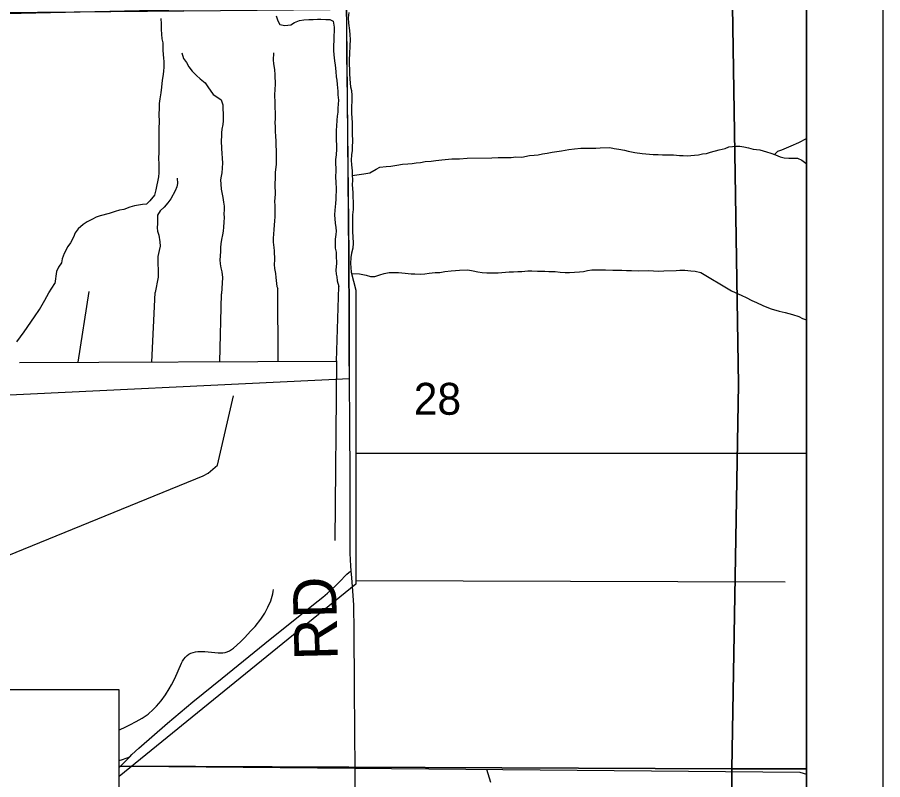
# Model space of a CAD drawing. Extents: x 0 to 34, y 0 to 22.
# Drawn here: x 7.864 to 9, y 16.861 to 17.862 of the extents above; entities that cross this region are included whole.
import ezdxf

# ---------------------------------------------------------------- set-up
doc = ezdxf.new("R2010")
doc.units = 0
for name, color, linetype in [('Default', 7, 'Continuous'), ('GM_X_County_Road', 7, 'Continuous'), ('GM_X_County_Road_Text', 7, 'Continuous'), ('GM_X_Minor_River', 7, 'Continuous'), ('GM_X_Section', 7, 'Continuous'), ('GM_X_Section_Text', 7, 'Continuous'), ('GM_X_State_Route', 7, 'Continuous'), ('GM_X_Township_Road', 7, 'Continuous'), ('SH_Data', 7, 'Continuous'), ('SH_Text', 7, 'Continuous')]:
    doc.layers.add(name, color=color, linetype=linetype)

msp = doc.modelspace()

# ---------------------------------------------------------------- linework, layer by layer
at = {"layer": 'Default'}
msp.add_lwpolyline([(7.7898, 17.3636), (8.3, 17.3879), (8.2997, 17.4193), (8.2996, 17.4628), (8.2992, 17.5498), (8.2973, 17.7551), (8.2966, 17.8142), (8.2964, 17.8483), (8.296, 17.8766), (8.2922, 18.636), (8.2732, 18.6304), (8.2109, 18.6013), (8.1114, 18.5961), (8.102, 18.6855), (8.2128, 18.6932), (8.2343, 18.6339), (8.2922, 18.6449), (8.2909, 18.8461), (8.0037, 18.8355), (8.0219, 18.883), (8.0085, 18.8827), (8.0194, 18.9112)], dxfattribs=at)
for points in [[(8.9, 16.8757), (8.9, 17.8804), (8.8027, 17.8763), (8.8106, 17.3801), (8.802, 16.8756)], [(8.9, 15.8688), (8.9, 16.8757), (8.802, 16.8756), (8.808, 15.8683)]]:
    msp.add_lwpolyline(points, close=True, dxfattribs=at)
at = {"layer": 'GM_X_County_Road'}
for points in [[(8.3002, 17.3874), (8.2999, 17.4187), (8.2998, 17.4622), (8.2994, 17.5493), (8.2975, 17.7545), (8.2968, 17.8136), (8.2966, 17.8478), (8.2963, 17.8707), (8.2962, 17.8761)], [(8.3024, 17.1352), (8.3017, 17.1426), (8.3014, 17.1494), (8.301, 17.159), (8.3009, 17.1867), (8.3008, 17.2585), (8.3004, 17.3272), (8.3002, 17.3874)], [(8.3076, 16.8206), (8.3073, 16.8765), (8.3068, 16.923), (8.3067, 16.9851), (8.3062, 17.0565), (8.3055, 17.0906), (8.3045, 17.1092), (8.3035, 17.1208), (8.3027, 17.1315), (8.3024, 17.1352)]]:
    msp.add_lwpolyline(points, dxfattribs=at)
at = {"layer": 'GM_X_Minor_River'}
for p, q in [((8.3083, 17.2899), (8.9, 17.2898)), ((8.8911, 16.8713), (8.9, 16.8685))]:
    msp.add_line(p, q, dxfattribs=at)
for points in [[(8.0524, 17.8601), (8.0529, 17.8532), (8.0529, 17.846), (8.0534, 17.8396), (8.0535, 17.8335), (8.0551, 17.8282), (8.0551, 17.8232), (8.0548, 17.8183), (8.0557, 17.8084), (8.0562, 17.8039), (8.0562, 17.797), (8.056, 17.7906), (8.0549, 17.7841), (8.0542, 17.7792), (8.0532, 17.77), (8.0521, 17.7628), (8.0511, 17.7548), (8.05, 17.7487), (8.0501, 17.7419), (8.0498, 17.735), (8.05, 17.7244), (8.0497, 17.7168), (8.0499, 17.7009), (8.0496, 17.6929), (8.0497, 17.6838), (8.0494, 17.6781), (8.0496, 17.6682), (8.0497, 17.6576), (8.0494, 17.6526), (8.0458, 17.6355), (8.044, 17.6286), (8.038, 17.6209), (8.0335, 17.6167), (8.0282, 17.6162), (8.0232, 17.6154), (8.0179, 17.6146), (8.0115, 17.6126), (8.0039, 17.6098), (7.9982, 17.6086), (7.9922, 17.607), (7.9846, 17.6046), (7.9725, 17.6014), (7.9675, 17.5995), (7.9626, 17.5971), (7.9558, 17.5936), (7.9505, 17.5898), (7.9438, 17.5843), (7.94, 17.579), (7.9378, 17.5733), (7.9337, 17.566), (7.93, 17.561), (7.9252, 17.5518), (7.9226, 17.5449), (7.9219, 17.5396), (7.9178, 17.5339), (7.9152, 17.5281), (7.9131, 17.5127)], [(8.2037, 17.8636), (8.2057, 17.8572), (8.2084, 17.8523), (8.2149, 17.8512), (8.2229, 17.8521), (8.2278, 17.8552), (8.2342, 17.8575), (8.2399, 17.8587), (8.2467, 17.8592), (8.2525, 17.8589), (8.2578, 17.8594), (8.2623, 17.8594), (8.2688, 17.8588), (8.2741, 17.8588), (8.2787, 17.8566), (8.28, 17.849), (8.2797, 17.8437), (8.2794, 17.8376), (8.2794, 17.8327), (8.2788, 17.8236), (8.2788, 17.8182), (8.2793, 17.8125), (8.2805, 17.8046), (8.281, 17.7989), (8.2819, 17.7909), (8.2823, 17.7837), (8.2832, 17.7792), (8.2836, 17.7735), (8.2845, 17.7651), (8.2845, 17.7602), (8.2854, 17.753), (8.2851, 17.7477), (8.2848, 17.7427), (8.2845, 17.7374), (8.2838, 17.7321), (8.2835, 17.7271), (8.2828, 17.7191), (8.2825, 17.7138), (8.2827, 17.6998), (8.2831, 17.6948), (8.2828, 17.6888), (8.2825, 17.6815), (8.2818, 17.6751), (8.2815, 17.6694), (8.282, 17.6641), (8.2821, 17.6591), (8.2817, 17.6538), (8.2819, 17.6439), (8.2823, 17.6386), (8.2824, 17.6333), (8.2821, 17.628), (8.2821, 17.6234), (8.2815, 17.6177), (8.2808, 17.6086), (8.2805, 17.6025), (8.2814, 17.5919), (8.2819, 17.5862), (8.2823, 17.5813), (8.282, 17.5767), (8.2813, 17.5706), (8.281, 17.5634), (8.2811, 17.5588), (8.2823, 17.5535), (8.2827, 17.549), (8.2829, 17.5391), (8.2822, 17.53), (8.2827, 17.525), (8.2835, 17.5212), (8.2837, 17.5161), (8.2858, 17.5084)], [(8.2991, 17.8683), (8.2984, 17.8614), (8.2989, 17.8542), (8.3002, 17.8444), (8.3003, 17.839), (8.3007, 17.8326), (8.3004, 17.8246), (8.2998, 17.814), (8.2995, 17.8064), (8.2996, 17.8003), (8.3001, 17.7931), (8.3002, 17.7881), (8.3006, 17.7805), (8.3015, 17.7707)], [(8.08, 17.8152), (8.082, 17.808), (8.0862, 17.8024), (8.089, 17.7971), (8.0936, 17.7911), (8.099, 17.7855), (8.104, 17.7813), (8.1105, 17.7761), (8.114, 17.7708), (8.121, 17.7607), (8.126, 17.7577), (8.1317, 17.7536), (8.1337, 17.7468), (8.1338, 17.7422), (8.1343, 17.7346), (8.134, 17.7259), (8.1337, 17.7213), (8.1326, 17.7149), (8.1319, 17.7103), (8.132, 17.7057), (8.1317, 17.7004), (8.1318, 17.6894), (8.1323, 17.6837), (8.1327, 17.6765), (8.1332, 17.6708), (8.1329, 17.664), (8.1326, 17.6579), (8.1315, 17.6533), (8.1308, 17.6488), (8.1309, 17.6427), (8.1317, 17.6362), (8.133, 17.6298), (8.1338, 17.6252), (8.1346, 17.6192), (8.1354, 17.6142), (8.1355, 17.6093), (8.1352, 17.604), (8.1353, 17.5991), (8.135, 17.593), (8.1347, 17.5865), (8.134, 17.5812), (8.1333, 17.5766), (8.1318, 17.5701), (8.1311, 17.5648), (8.1305, 17.5599), (8.1305, 17.5549), (8.1302, 17.5485), (8.1299, 17.5435), (8.13, 17.5382), (8.1312, 17.5329), (8.1324, 17.528), (8.1332, 17.5204), (8.1318, 17.4989)], [(8.2002, 17.8153), (8.1999, 17.8058), (8.2003, 17.8012), (8.2016, 17.7929), (8.202, 17.7868), (8.2022, 17.7732), (8.2019, 17.7678), (8.2016, 17.7591), (8.2021, 17.7504), (8.2018, 17.7458), (8.2023, 17.7344), (8.2024, 17.7287), (8.2021, 17.7238), (8.2022, 17.7181), (8.2026, 17.712), (8.2027, 17.7059), (8.2032, 17.6995), (8.2033, 17.6938), (8.2037, 17.6873), (8.2039, 17.6763), (8.2036, 17.6691), (8.2026, 17.6584), (8.2023, 17.6516), (8.202, 17.6425), (8.2022, 17.63), (8.2015, 17.6201), (8.202, 17.6148), (8.2021, 17.6045), (8.2018, 17.5999), (8.2015, 17.595), (8.2012, 17.5889), (8.2005, 17.5836), (8.2002, 17.5771), (8.1999, 17.5722), (8.1996, 17.5669), (8.2008, 17.56), (8.2012, 17.5555), (8.2014, 17.5437), (8.2011, 17.5376), (8.2015, 17.5323), (8.2028, 17.5255), (8.2032, 17.5206), (8.2045, 17.5084), (8.206, 17.5061)], [(8.3015, 17.7707), (8.3027, 17.7658), (8.3032, 17.7593), (8.3029, 17.7525), (8.3026, 17.7441), (8.3027, 17.7357), (8.3032, 17.7301), (8.3037, 17.7236), (8.3034, 17.7171), (8.3035, 17.7092), (8.304, 17.6993), (8.3037, 17.6921), (8.3034, 17.6871), (8.3027, 17.6814), (8.3024, 17.6742), (8.3025, 17.6681), (8.3033, 17.6605), (8.3034, 17.6556), (8.3039, 17.6476), (8.3036, 17.6423), (8.3045, 17.6317), (8.3045, 17.6264), (8.305, 17.6195), (8.3047, 17.6146), (8.3048, 17.6097), (8.3041, 17.6028), (8.3038, 17.5979), (8.304, 17.5804), (8.3045, 17.574), (8.3046, 17.5656), (8.3043, 17.5591), (8.3028, 17.5523), (8.3018, 17.5466), (8.3015, 17.5386), (8.3016, 17.5336), (8.302, 17.5276), (8.3085, 17.5036)], [(8.8578, 17.682), (8.8625, 17.6862), (8.8678, 17.6878), (8.8799, 17.6933), (8.8897, 17.6976), (8.9, 17.7027)], [(8.3035, 17.6541), (8.319, 17.6566), (8.3266, 17.6578), (8.3349, 17.6625), (8.3398, 17.6652), (8.3481, 17.6661), (8.3542, 17.6665), (8.3622, 17.6678), (8.3694, 17.669), (8.3766, 17.6695), (8.3823, 17.67), (8.3876, 17.6708), (8.393, 17.6712), (8.3994, 17.6725), (8.407, 17.6733), (8.4135, 17.6738), (8.4214, 17.675), (8.4344, 17.676), (8.4442, 17.6761), (8.4545, 17.677), (8.4868, 17.6774), (8.4952, 17.6779), (8.507, 17.6777), (8.5123, 17.6778), (8.5184, 17.6786), (8.5264, 17.6783), (8.5362, 17.6804), (8.5423, 17.6808), (8.5476, 17.6816), (8.5533, 17.6829), (8.5594, 17.6837), (8.5662, 17.6849), (8.5784, 17.6866), (8.5879, 17.6883), (8.5954, 17.6891), (8.6038, 17.69), (8.6232, 17.6902), (8.6289, 17.6907), (8.6418, 17.6909), (8.6475, 17.6898), (8.6536, 17.6888), (8.6609, 17.6877), (8.6658, 17.6863), (8.6746, 17.6845), (8.6841, 17.6831), (8.6986, 17.6818), (8.7051, 17.6818), (8.7108, 17.6815), (8.718, 17.6816), (8.7252, 17.6813), (8.7332, 17.6807), (8.7382, 17.6804), (8.7435, 17.6801), (8.753, 17.681), (8.7583, 17.6814), (8.7636, 17.6826), (8.7686, 17.6831), (8.7739, 17.685), (8.7853, 17.6878), (8.7932, 17.6898), (8.7981, 17.6918), (8.8076, 17.6927), (8.8126, 17.6928), (8.8179, 17.6921), (8.824, 17.6906), (8.8301, 17.6888), (8.8385, 17.6878), (8.8473, 17.6852), (8.853, 17.6834), (8.8591, 17.6816), (8.8652, 17.6787), (8.8706, 17.6776), (8.8767, 17.6769), (8.8881, 17.6771), (8.8938, 17.6745), (8.8992, 17.6704), (8.9, 17.6692)], [(8.0737, 17.6507), (8.0742, 17.6438), (8.0731, 17.6392), (8.0713, 17.6343), (8.0653, 17.6236), (8.0616, 17.6182), (8.0567, 17.6128), (8.0515, 17.6078), (8.0481, 17.6024), (8.0478, 17.596), (8.0479, 17.5911), (8.0476, 17.5857), (8.048, 17.5812), (8.0496, 17.5759), (8.0512, 17.5672), (8.0513, 17.5615), (8.0503, 17.5558), (8.0485, 17.5481), (8.0488, 17.5208), (8.0448, 17.5008)], [(8.302, 17.5256), (8.3131, 17.5254), (8.3219, 17.5233), (8.3276, 17.5218), (8.3333, 17.5219), (8.3397, 17.5239), (8.3454, 17.5255), (8.3522, 17.5271), (8.3587, 17.5272), (8.3644, 17.5269), (8.3732, 17.5259), (8.3808, 17.5252), (8.3857, 17.5253), (8.3933, 17.525), (8.3987, 17.5251), (8.4044, 17.5259), (8.4123, 17.5268), (8.4184, 17.5272), (8.4252, 17.5285), (8.4336, 17.5293), (8.4393, 17.5294), (8.4446, 17.5302), (8.4553, 17.5304), (8.4625, 17.529), (8.4686, 17.5279), (8.4743, 17.5268), (8.4804, 17.5265), (8.4952, 17.5267), (8.5097, 17.5277), (8.5154, 17.5278), (8.5211, 17.5282), (8.5264, 17.5283), (8.534, 17.5291), (8.5393, 17.5292), (8.5466, 17.5289), (8.5565, 17.5287), (8.5618, 17.5284), (8.5698, 17.5285), (8.5766, 17.5274), (8.5831, 17.5268), (8.5888, 17.5268), (8.5953, 17.5273), (8.6021, 17.5278), (8.6074, 17.5282), (8.6123, 17.5298), (8.618, 17.5306), (8.6245, 17.5307), (8.6302, 17.5304), (8.6359, 17.5305), (8.6458, 17.5302), (8.6508, 17.5299), (8.6576, 17.53), (8.6637, 17.5297), (8.6702, 17.5298), (8.6793, 17.5292), (8.693, 17.5294), (8.6991, 17.5291), (8.7055, 17.5288), (8.7128, 17.5292), (8.7287, 17.5295), (8.7337, 17.5299), (8.7401, 17.53), (8.7481, 17.5293), (8.7539, 17.5286), (8.7611, 17.5272), (8.7995, 17.5043)], [(7.8632, 17.4358), (7.8729, 17.4491), (7.8865, 17.4689), (7.8928, 17.4785), (7.9, 17.4906), (7.9052, 17.5002), (7.9131, 17.5127)], [(8.2828, 17.4105), (8.2858, 17.5084)], [(7.9439, 17.4092), (7.9582, 17.5019)], [(8.3085, 17.5036), (8.3081, 17.118), (7.9975, 16.8656), (7.9972, 16.8653)], [(8.0403, 17.4095), (8.0448, 17.5008)], [(8.1296, 17.4099), (8.1318, 17.4989)], [(8.2064, 17.4102), (8.206, 17.5061)], [(8.7995, 17.5043), (8.8014, 17.5031), (8.8151, 17.497), (8.8208, 17.494), (8.8283, 17.4902), (8.8344, 17.4875), (8.8427, 17.4837), (8.8477, 17.4814), (8.8534, 17.4791), (8.864, 17.4764), (8.8719, 17.4745), (8.8814, 17.4718), (8.8897, 17.4692), (8.8946, 17.4665), (8.9, 17.4648)], [(7.8667, 17.4089), (8.2836, 17.4105)], [(8.2828, 17.4105), (8.2806, 17.1755)], [(7.6537, 17.1508), (7.699, 17.1181), (7.7047, 17.1128), (7.7153, 17.1095), (7.7335, 17.1077), (8.108, 17.2601), (8.1144, 17.2635), (8.1269, 17.2742), (8.1476, 17.365)], [(8.3081, 17.1226), (8.8721, 17.121)], [(8.0141, 16.8791), (8.8911, 16.8713)], [(8.48, 16.875), (8.4852, 16.858)]]:
    msp.add_lwpolyline(points, dxfattribs=at)
at = {"layer": 'GM_X_Section'}
for points in [[(7.9972, 16.8792), (8.802, 16.8756), (8.8106, 17.3801), (8.8027, 17.8763), (7.7942, 17.8673), (7.7942, 17.5709), (7.8062, 16.9797), (7.9972, 16.9797)], [(7.8054, 16.2626), (7.8036, 15.873), (7.8312, 15.8725), (8.808, 15.8683), (8.802, 16.8756), (7.9972, 16.8792), (7.9972, 16.2626)]]:
    msp.add_lwpolyline(points, close=True, dxfattribs=at)
at = {"layer": 'GM_X_State_Route'}
msp.add_lwpolyline([(7.8042, 16.2626), (7.8024, 15.8725), (6.7968, 15.8774), (5.6416, 15.8841), (5.6436, 15.468), (5.6455, 14.1), (8.9, 14.1), (8.9, 18.8876), (8.7984, 18.8872), (8.8033, 17.8763), (8.296, 17.8766), (7.7904, 17.865), (7.8038, 16.9797), (7.9972, 16.9797), (7.9972, 16.2626)], close=True, dxfattribs=at)
at = {"layer": 'GM_X_Township_Road'}
for points in [[(7.9972, 16.8771), (7.9991, 16.8788), (8.0116, 16.8916), (8.0142, 16.8943), (8.0233, 16.9027), (8.0609, 16.9354), (8.0942, 16.9635), (8.133, 16.9946), (8.1957, 17.0458), (8.2589, 17.096), (8.2648, 17.1008), (8.2712, 17.106), (8.2757, 17.1102), (8.2825, 17.1165), (8.2891, 17.1232), (8.2939, 17.1286), (8.2964, 17.1311), (8.299, 17.1332), (8.3008, 17.1345), (8.3024, 17.1352)], [(7.9972, 16.9262), (8.0072, 16.9313), (8.0115, 16.9333), (8.0198, 16.9376), (8.028, 16.9423), (8.0306, 16.9439), (8.0355, 16.9475), (8.0422, 16.9536), (8.0466, 16.958), (8.0527, 16.9651), (8.0583, 16.9726), (8.0633, 16.9806), (8.0664, 16.986), (8.0705, 16.9943), (8.0795, 17.0142), (8.0809, 17.017), (8.0826, 17.0196), (8.0845, 17.022), (8.0867, 17.0242), (8.0892, 17.026), (8.0919, 17.0275), (8.0949, 17.0285), (8.0979, 17.0292), (8.101, 17.0296), (8.1041, 17.0298), (8.11, 17.0296), (8.1274, 17.028), (8.1305, 17.0279), (8.1336, 17.028), (8.1366, 17.0284), (8.1396, 17.0292), (8.1424, 17.0305), (8.1449, 17.0321), (8.1475, 17.0339), (8.152, 17.0378), (8.1572, 17.0426), (8.1625, 17.0478), (8.1702, 17.0562), (8.176, 17.0623), (8.1838, 17.072), (8.1887, 17.0799), (8.193, 17.088), (8.1966, 17.0963), (8.1986, 17.1022), (8.1994, 17.1052), (8.2, 17.1082), (8.2003, 17.1112)], [(7.9972, 16.8864), (7.9974, 16.8864), (8.0022, 16.888), (8.0069, 16.8898), (8.0116, 16.8916)]]:
    msp.add_lwpolyline(points, dxfattribs=at)
at = {"layer": 'SH_Data'}
for p, q in [((9, 21), (9, 14)), ((8.9, 20.9), (8.9, 14.1))]:
    msp.add_line(p, q, dxfattribs=at)
at = {"layer": 'SH_Text'}
msp.add_lwpolyline([(5.7774, 16.9797), (7.9972, 16.9797), (7.9972, 16.2626), (5.7774, 16.2626)], close=True, dxfattribs=at)

# ---------------------------------------------------------------- texts
at = {"layer": 'GM_X_County_Road_Text'}
msp.add_text('RD', height=0.05682, rotation=91.4141, dxfattribs=at).set_placement((8.2847, 17.0188))
at = {"layer": 'GM_X_Section_Text'}
msp.add_text('28', height=0.04186, rotation=0, dxfattribs=at).set_placement((8.3843, 17.3403))

doc.saveas('drawing.dxf')
